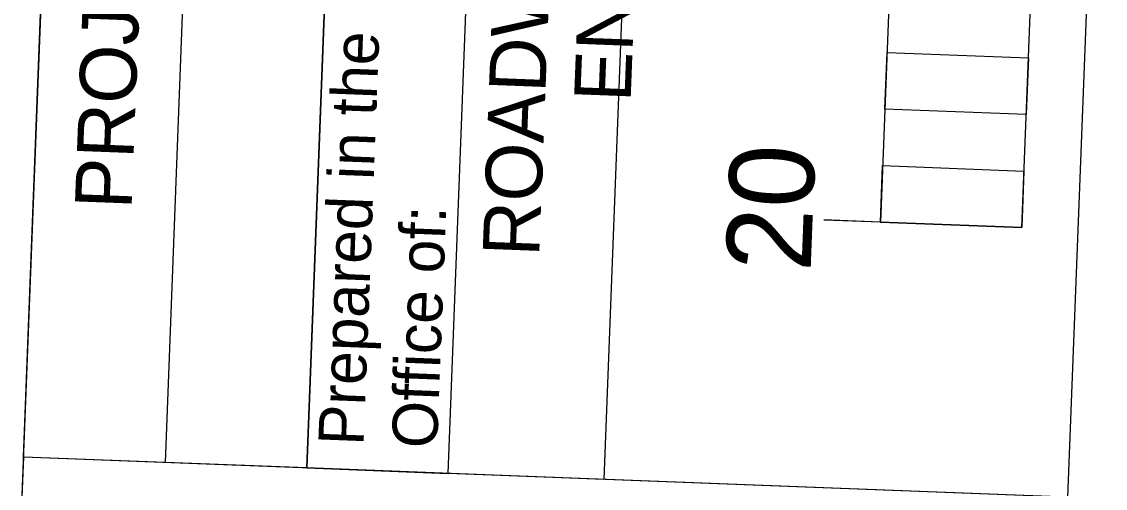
# Model space of a CAD drawing. Extents: x 2097431 to 2097897, y 685861 to 686794.
# Drawn here: x 2097463.62 to 2097501.92, y 686607.1 to 686623.59 of the extents above; entities that cross this region are included whole.
import ezdxf

# ---------------------------------------------------------------- set-up
doc = ezdxf.new("R2010")
doc.units = 0
for name, color, linetype in [('Scratch_Level_5', 7, 'Continuous'), ('Sheet Block Title CELL', 7, 'Continuous'), ('Sheet Data Field CELL', 7, 'Continuous'), ('Sheet Plan And Profile CELL', 7, 'Continuous'), ('Sheet Profile CELL', 7, 'Continuous'), ('Sheet Title CELL', 7, 'Continuous')]:
    doc.layers.add(name, color=color, linetype=linetype)

msp = doc.modelspace()

# ---------------------------------------------------------------- linework, layer by layer
at = {"layer": 'Scratch_Level_5'}
msp.add_lwpolyline([(2097443.756, 686088.61), (2097699.444, 686078.804), (2097722.438, 686678.363), (2097503.654, 686686.754), (2097500.587, 686606.792), (2097463.684, 686608.208)], close=True, dxfattribs=at)
at = {"layer": 'Sheet Block Title CELL'}
msp.add_lwpolyline([(2097473.696, 686607.824), (2097476.763, 686687.788), (2097487.258, 686687.386), (2097484.191, 686607.421)], close=True, dxfattribs=at)
at = {"layer": 'Sheet Data Field CELL'}
msp.add_line((2097493.967, 686616.513), (2097491.974, 686616.59), dxfattribs=at)
at = {"layer": 'Sheet Plan And Profile CELL'}
for p, q in [((2097468.7, 686608.015), (2097471.767, 686687.976)), ((2097473.696, 686607.824), (2097476.763, 686687.785)), ((2097473.696, 686607.824), (2097478.693, 686607.632))]:
    msp.add_line(p, q, dxfattribs=at)
for points in [[(2097466.75, 686688.169), (2097443.756, 686088.61), (2097863.448, 686072.514), (2097886.442, 686672.073)], [(2097463.684, 686608.208), (2097466.75, 686688.169), (2097476.763, 686687.785), (2097473.696, 686607.824)], [(2097478.693, 686607.632), (2097480.226, 686647.623), (2097525.193, 686645.898), (2097523.66, 686605.907)]]:
    msp.add_lwpolyline(points, close=True, dxfattribs=at)
at = {"layer": 'Sheet Profile CELL'}
msp.add_line((2097468.7, 686608.015), (2097471.767, 686687.976), dxfattribs=at)
for points in [[(2097466.75, 686688.169), (2097443.756, 686088.61), (2097863.448, 686072.514), (2097886.442, 686672.073)], [(2097463.684, 686608.208), (2097466.75, 686688.169), (2097476.763, 686687.785), (2097473.696, 686607.824)]]:
    msp.add_lwpolyline(points, close=True, dxfattribs=at)
at = {"layer": 'Sheet Title CELL'}
for p, q in [((2097496.271, 686676.464), (2097493.972, 686616.508)), ((2097498.968, 686616.316), (2097501.273, 686676.272)), ((2097493.972, 686616.508), (2097491.978, 686616.585)), ((2097491.978, 686616.585), (2097491.978, 686616.585)), ((2097493.972, 686616.508), (2097498.968, 686616.316)), ((2097493.972, 686616.508), (2097493.972, 686616.508))]:
    msp.add_line(p, q, dxfattribs=at)
for points in [[(2097494.125, 686620.505), (2097494.207, 686622.503), (2097499.203, 686622.312), (2097499.127, 686620.318)], [(2097493.972, 686616.508), (2097494.049, 686618.507), (2097499.045, 686618.315), (2097498.968, 686616.316)]]:
    msp.add_lwpolyline(points, close=True, dxfattribs=at)

# ---------------------------------------------------------------- texts
at = {"layer": 'Sheet Block Title CELL'}
for s, height, p in [('Prepared in the ', 1.60046, (2097475.701, 686608.596)), ('Office of:', 1.6005, (2097478.3, 686608.497))]:
    msp.add_text(s, height=height, rotation=87.8037, dxfattribs=at).set_placement(p)
at = {"layer": 'Sheet Data Field CELL'}
msp.add_text('20', height=3, rotation=87.8037, dxfattribs=at).set_placement((2097491.502, 686614.734))
at = {"layer": 'Sheet Plan And Profile CELL'}
for s, height, p in [('PROJECT REFERENCE NO.', 2.00004, (2097467.501, 686616.948)), ('ROADWAY DESIGN', 2.00004, (2097481.908, 686615.274)), ('ENGINEER', 2, (2097485.14, 686620.735))]:
    msp.add_text(s, height=height, rotation=87.8037, dxfattribs=at).set_placement(p)
at = {"layer": 'Sheet Profile CELL'}
msp.add_text('PROJECT REFERENCE NO.', height=2.00004, rotation=87.8037, dxfattribs=at).set_placement((2097467.497, 686616.953))

doc.saveas('drawing.dxf')
